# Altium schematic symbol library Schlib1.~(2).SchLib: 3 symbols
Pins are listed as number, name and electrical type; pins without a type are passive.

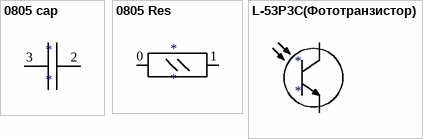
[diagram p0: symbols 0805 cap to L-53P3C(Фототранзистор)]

## 0805 cap
designator *
pins: 2, 3

## 0805 Res
designator *
pins: 0, 1

## L-53P3C(Фототранзистор)
designator *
